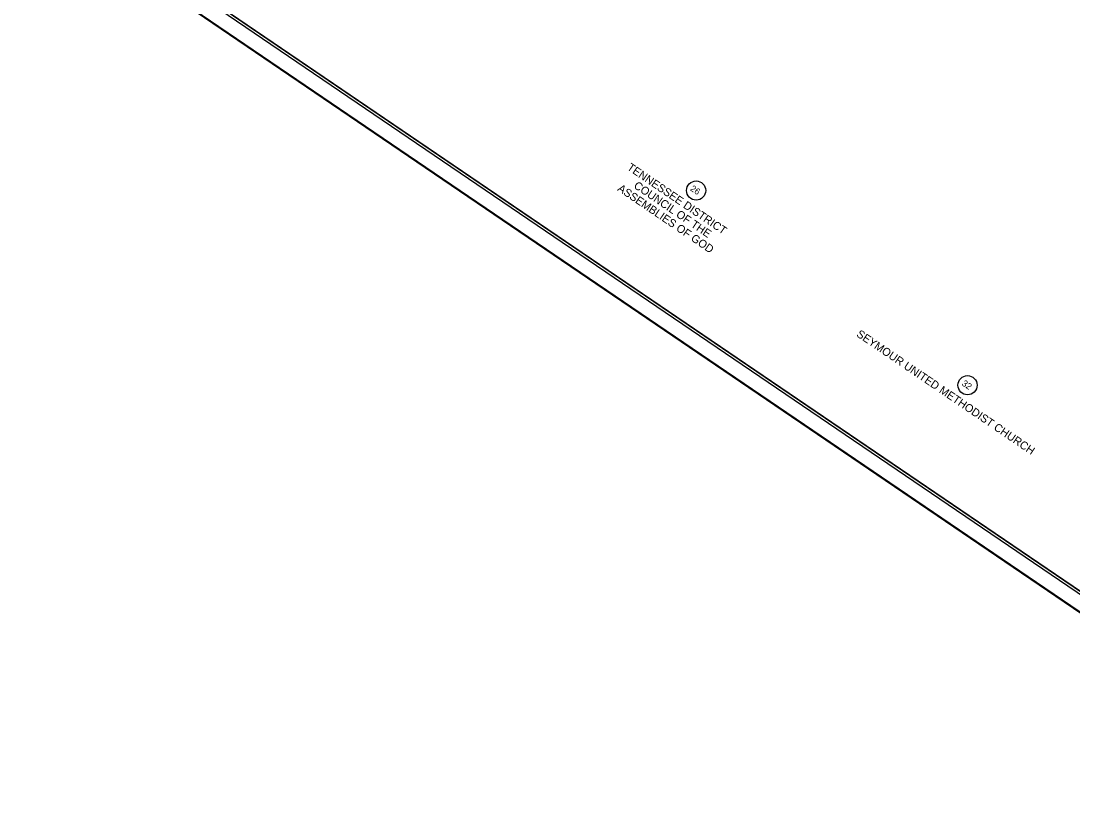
# Model space of a CAD drawing. Extents: x 2629906 to 2632029, y 567681 to 569670.
# Drawn here: x 2629906 to 2631056, y 567747 to 568618 of the extents above; entities that cross this region are included whole.
import ezdxf

# ---------------------------------------------------------------- set-up
doc = ezdxf.new("R2010")
doc.units = 0
for name, color, linetype in [('DESIGN - SHEET - Light Grid', 7, 'Continuous'), ('DESIGN - SHEET - Linework', 7, 'Continuous'), ('DESIGN - SHEET - Plot Shape', 7, 'Continuous'), ('SURVEY - PROPERTY - Owners', 7, 'Continuous'), ('SURVEY - PROPERTY - Tract Numbers', 7, 'Continuous')]:
    doc.layers.add(name, color=color, linetype=linetype)

msp = doc.modelspace()

# ---------------------------------------------------------------- linework, layer by layer
at = {"layer": 'DESIGN - SHEET - Light Grid'}
msp.add_lwpolyline([(2630011.2, 568707.4), (2631387.9, 567770.9), (2631981.3, 568643.2), (2630604.6, 569579.7)], close=True, dxfattribs=at)
at = {"layer": 'DESIGN - SHEET - Linework'}
msp.add_line((2629906.4, 568759.1), (2631394.7, 567746.7), dxfattribs=at)
msp.add_lwpolyline([(2630673.6, 569529.8), (2630083, 568661.6), (2631384.6, 567776.2), (2631975.1, 568644.4), (2630673.6, 569529.8)], dxfattribs=at)
at = {"layer": 'DESIGN - SHEET - Plot Shape'}
for points in [[(2630588.8, 569611.3), (2631994.4, 568655.1), (2631381.6, 567754.4), (2629976, 568710.6)], [(2630603.2, 569577.6), (2631975.1, 568644.4), (2631384.6, 567776.2), (2630012.6, 568709.5)]]:
    msp.add_lwpolyline(points, close=True, dxfattribs=at)
at = {"layer": 'SURVEY - PROPERTY - Tract Numbers'}
for centre in [(2630644.1, 568432.5), (2630940.7, 568219.7)]:
    msp.add_circle(centre, 10.5, dxfattribs=at)

# ---------------------------------------------------------------- texts
at = {"layer": 'SURVEY - PROPERTY - Owners'}
for s, p in [('TENNESSEE DISTRICT', (2630567.9, 568456)), ('ASSEMBLIES OF GOD', (2630557.5, 568432.9)), ('COUNCIL OF THE', (2630575.2, 568436)), ('SEYMOUR UNITED METHODIST CHURCH', (2630818.6, 568273.7))]:
    msp.add_text(s, height=8.75, rotation=325.7738, dxfattribs=at).set_placement(p)
at = {"layer": 'SURVEY - PROPERTY - Tract Numbers'}
for s, p in [('26', (2630637, 568433.1)), ('32', (2630933.8, 568220.1))]:
    msp.add_text(s, height=7, rotation=325.7738, dxfattribs=at).set_placement(p)

doc.saveas('drawing.dxf')
